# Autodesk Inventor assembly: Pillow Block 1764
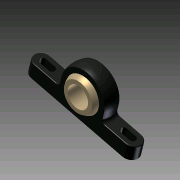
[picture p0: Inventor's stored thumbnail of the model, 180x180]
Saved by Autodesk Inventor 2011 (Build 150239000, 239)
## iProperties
Created: 2009-01
Part Number: Pillow Block 1764
Document SubType Name: Assembly
Designer: lwoods
Mass: 25.286 g
Surface Area: 91.7026 cm^2
Volume: 18.0615 cm^3
Density: 1.4 g/cm^3
Author: lwoods
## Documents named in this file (3)
- R:\CAD Archives\Pillow Block 1764\Pillow Block 1764.iam
- R:\CAD Archives\Pillow Block 1764\Pillow Bock Outer Piece 1764.ipt
- R:\CAD Archives\Pillow Block 1764\Pillow Block Inner Piece 1764.ipt
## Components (2 placed, 2 different names)
1. Pillow Bock Outer Piece 1764:1 — Tangent:1, Angle:1, Angle:2
2. Pillow Block Inner Piece 1764:1 — Tangent:1, Angle:1, Mate:1
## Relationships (4: Angle 2, Tangent 1, Mate 1)
- Tangent:1: Pillow Bock Outer Piece 1764:1 ↔ Pillow Block Inner Piece 1764:1
- Angle:1: Pillow Bock Outer Piece 1764:1 ↔ Pillow Block Inner Piece 1764:1
- Mate:1: Pillow Block Inner Piece 1764:1
- Angle:2: Pillow Bock Outer Piece 1764:1
